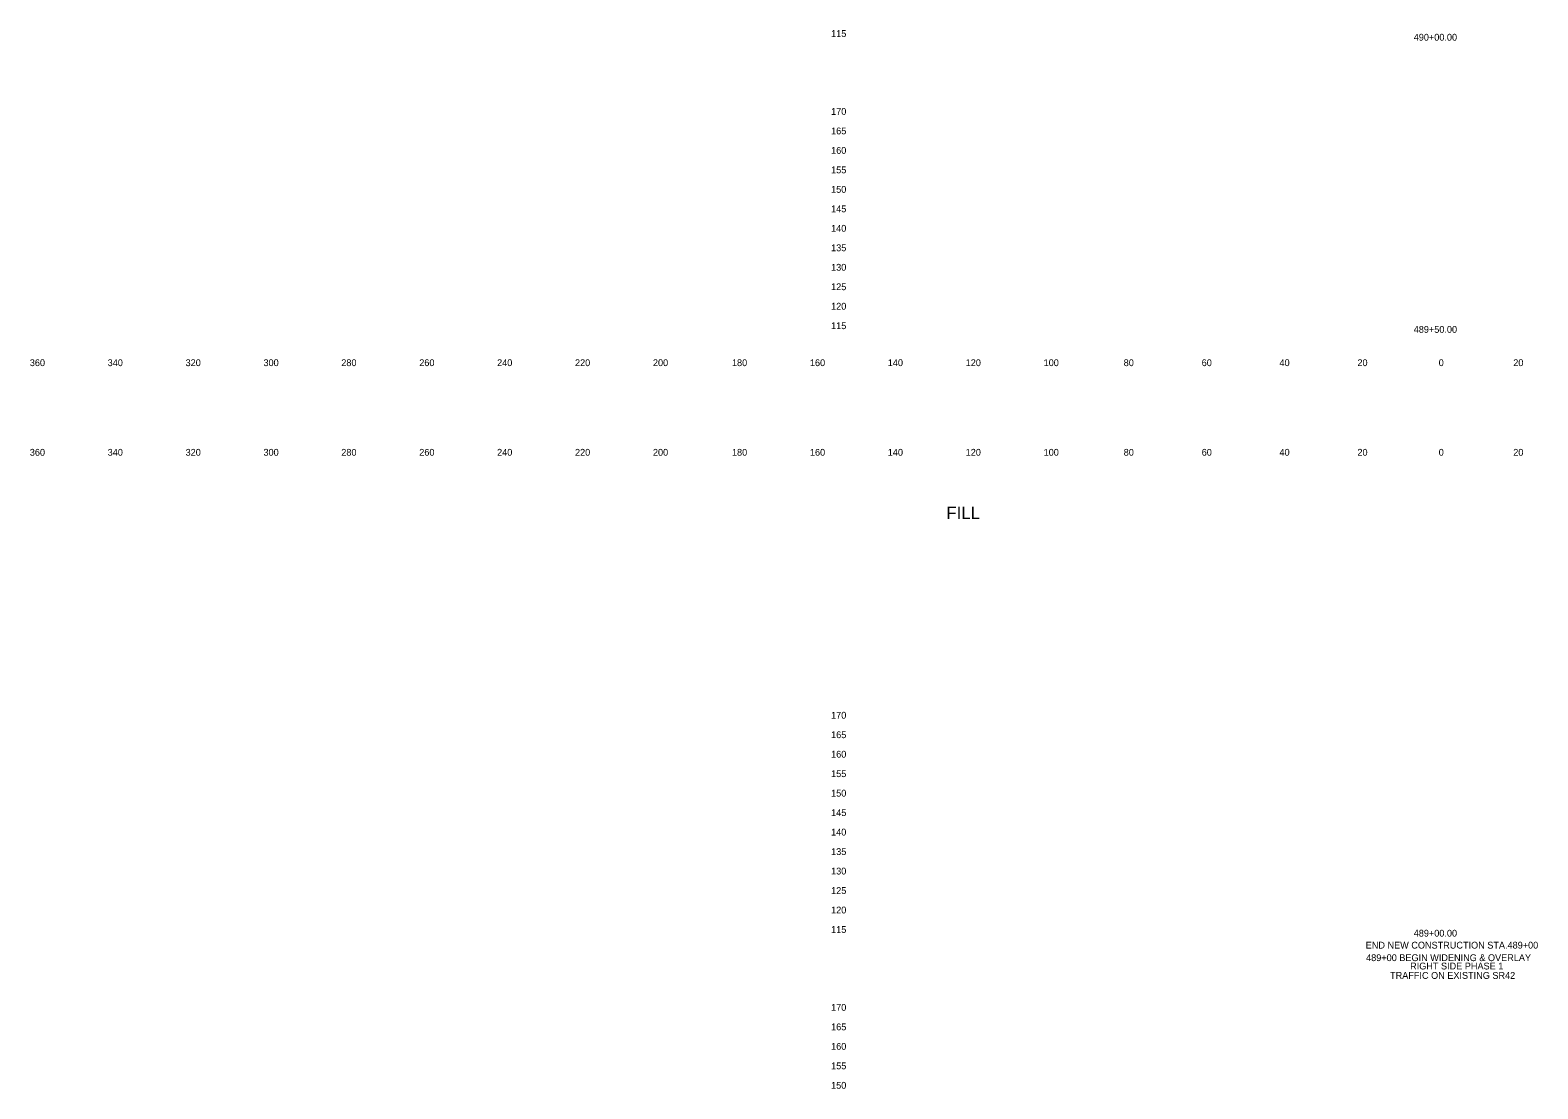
# Model space of a CAD drawing. Extents: x 21281 to 22024, y 6472 to 15198.
# Drawn here: x 21280.5 to 21667.6, y 14109.8 to 14381.6 of the extents above; entities that cross this region are included whole.
import ezdxf

# ---------------------------------------------------------------- set-up
doc = ezdxf.new("R2010")
doc.units = 0
for name, color, linetype in [('XS_SHEET_LABELS_ELEVATION', 7, 'Continuous'), ('XS_SHEET_LABELS_OFFSET', 7, 'Continuous'), ('XS_SHEET_LABELS_STATION', 7, 'Continuous')]:
    doc.layers.add(name, color=color, linetype=linetype)

msp = doc.modelspace()

# ---------------------------------------------------------------- texts
at = {"layer": 'XS_SHEET_LABELS_ELEVATION'}
for s, p in [('  115  ', (21484.84, 14379.84)), ('  170  ', (21484.84, 14359.84)), ('  165  ', (21484.84, 14354.84)), ('  160  ', (21484.84, 14349.84)), ('  155  ', (21484.84, 14344.84)), ('  150  ', (21484.84, 14339.84)), ('  145  ', (21484.84, 14334.84)), ('  140  ', (21484.84, 14329.84)), ('  135  ', (21484.84, 14324.84)), ('  130  ', (21484.84, 14319.84)), ('  125  ', (21484.84, 14314.84)), ('  120  ', (21484.84, 14309.84)), ('  115  ', (21484.84, 14304.84)), ('  170  ', (21484.84, 14204.84)), ('  165  ', (21484.84, 14199.84)), ('  160  ', (21484.84, 14194.84)), ('  155  ', (21484.84, 14189.84)), ('  150  ', (21484.84, 14184.84)), ('  145  ', (21484.84, 14179.84)), ('  140  ', (21484.84, 14174.84)), ('  135  ', (21484.84, 14169.84)), ('  130  ', (21484.84, 14164.84)), ('  125  ', (21484.84, 14159.84)), ('  120  ', (21484.84, 14154.84)), ('  115  ', (21484.84, 14149.84)), ('  170  ', (21484.84, 14129.84)), ('  165  ', (21484.84, 14124.84)), ('  160  ', (21484.84, 14119.84)), ('  155  ', (21484.84, 14114.84)), ('  150  ', (21484.84, 14109.84))]:
    msp.add_text(s, height=1.75, dxfattribs=at).set_placement(p)
at = {"layer": 'XS_SHEET_LABELS_OFFSET'}
for s, height, p in [('  360  ', 1.75, (21279.14, 14295.34)), ('  340  ', 1.75, (21299.13, 14295.34)), ('  320  ', 1.75, (21319.13, 14295.34)), ('  300  ', 1.75, (21339.13, 14295.34)), ('  280  ', 1.75, (21359.1, 14295.34)), ('  260  ', 1.75, (21379.11, 14295.34)), ('  240  ', 1.75, (21399.1, 14295.34)), ('  220  ', 1.75, (21419.1, 14295.34)), ('  200  ', 1.75, (21439.1, 14295.34)), ('  180  ', 1.75, (21459.39, 14295.34)), ('  160  ', 1.75, (21479.4, 14295.34)), ('  140  ', 1.75, (21499.39, 14295.34)), ('  120  ', 1.75, (21519.39, 14295.34)), ('  100  ', 1.75, (21539.39, 14295.34)), ('  80  ', 1.75, (21559.95, 14295.34)), ('  60  ', 1.75, (21579.97, 14295.34)), ('  40  ', 1.75, (21599.95, 14295.34)), ('  20  ', 1.75, (21619.95, 14295.34)), ('  0  ', 1.75, (21640.81, 14295.34)), ('  0  ', 1.75, (21640.81, 14295.34)), ('  20  ', 1.75, (21659.95, 14295.34)), ('  360  ', 1.75, (21279.14, 14272.34)), ('  340  ', 1.75, (21299.13, 14272.34)), ('  320  ', 1.75, (21319.13, 14272.34)), ('  300  ', 1.75, (21339.13, 14272.34)), ('  280  ', 1.75, (21359.1, 14272.34)), ('  260  ', 1.75, (21379.11, 14272.34)), ('  240  ', 1.75, (21399.1, 14272.34)), ('  220  ', 1.75, (21419.1, 14272.34)), ('  200  ', 1.75, (21439.1, 14272.34)), ('  180  ', 1.75, (21459.39, 14272.34)), ('  160  ', 1.75, (21479.4, 14272.34)), ('  140  ', 1.75, (21499.39, 14272.34)), ('  120  ', 1.75, (21519.39, 14272.34)), ('  100  ', 1.75, (21539.39, 14272.34)), ('  80  ', 1.75, (21559.95, 14272.34)), ('  60  ', 1.75, (21579.97, 14272.34)), ('  40  ', 1.75, (21599.95, 14272.34)), ('  20  ', 1.75, (21619.95, 14272.34)), ('  0  ', 1.75, (21640.81, 14272.34)), ('  0  ', 1.75, (21640.81, 14272.34)), ('  20  ', 1.75, (21659.95, 14272.34)), ('FILL', 3.222, (21515.74, 14256.06))]:
    msp.add_text(s, height=height, dxfattribs=at).set_placement(p)
at = {"layer": 'XS_SHEET_LABELS_STATION'}
for s, p in [('  490+00.00  ', (21634.4, 14378.89)), ('  489+50.00  ', (21634.4, 14303.89)), ('  489+00.00  ', (21634.4, 14148.89)), ('  489+00.00  ', (21634.4, 14148.89)), ('  489+00.00  ', (21634.4, 14148.89)), ('  489+00.00  ', (21634.4, 14148.89)), ('  489+00.00  ', (21634.4, 14148.89)), ('END NEW CONSTRUCTION STA.489+00 ', (21623.38, 14145.82)), (' 489+00 BEGIN WIDENING & OVERLAY', (21622.83, 14142.6)), ('TRAFFIC ON EXISTING SR42', (21629.63, 14138.05)), ('RIGHT SIDE PHASE 1', (21634.77, 14140.46))]:
    msp.add_text(s, height=1.75, dxfattribs=at).set_placement(p)

doc.saveas('drawing.dxf')
